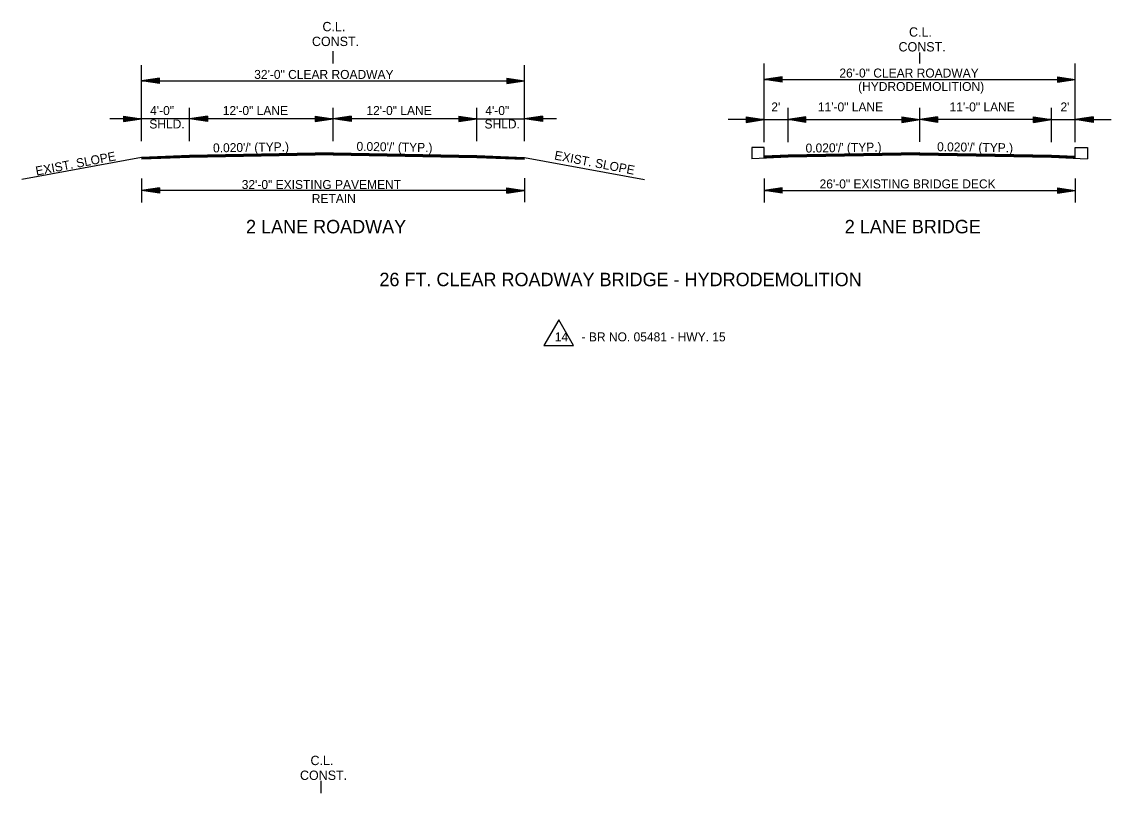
# Model space of a CAD drawing. Extents: x 549600 to 1930787, y -1955432 to 596640.
# Drawn here: x 551102 to 552012, y -1951981 to -1951337 of the extents above; entities that cross this region are included whole.
import ezdxf

# ---------------------------------------------------------------- set-up
doc = ezdxf.new("R2010")
doc.units = 0
doc.layers.add('R_Border', color=7, linetype='Continuous')
doc.layers.add('S_AREA_CALC', color=7, linetype='Continuous')

msp = doc.modelspace()

# ---------------------------------------------------------------- linework, layer by layer
at = {"layer": 'R_Border'}
for p, q in [((551982.02, -1951418.62), (552012.02, -1951418.62)), ((551711.85, -1951441.93), (551711.84, -1951451.31)), ((551722.02, -1951441.93), (551711.85, -1951441.93)), ((551722.02, -1951450.73), (551722.02, -1951441.93)), ((551982.02, -1951450.73), (551982.02, -1951441.93)), ((551982.02, -1951441.93), (551992.18, -1951441.93)), ((551992.18, -1951441.93), (551992.2, -1951451.31)), ((551538.16, -1951607.28), (551562.96, -1951607.28))]:
    msp.add_line(p, q, dxfattribs=at)
msp.add_lwpolyline([(551562.96, -1951607.28), (551550.56, -1951585.81), (551538.16, -1951607.28)], dxfattribs=at)
at = {"layer": 'S_AREA_CALC'}
for p, q in [((551362.02, -1951371.79), (551362.02, -1951361.42)), ((551852.02, -1951371.67), (551852.02, -1951362.37)), ((551202.02, -1951436.68), (551202.02, -1951373.17)), ((551522.02, -1951436.68), (551522.02, -1951373.17)), ((551722.02, -1951437.45), (551722.02, -1951371.72)), ((551982.02, -1951437.45), (551982.02, -1951371.72)), ((551217.02, -1951384.01), (551202.02, -1951386.26)), ((551202.02, -1951386.26), (551522.02, -1951386.26)), ((551217.02, -1951388.51), (551202.02, -1951386.26)), ((551217.02, -1951384.39), (551204.52, -1951386.26)), ((551217.02, -1951388.14), (551204.52, -1951386.26)), ((551217.02, -1951384.77), (551207.1, -1951386.26)), ((551217.02, -1951387.75), (551207.1, -1951386.26)), ((551217.02, -1951385.14), (551209.6, -1951386.26)), ((551217.02, -1951387.38), (551209.6, -1951386.26)), ((551217.02, -1951385.53), (551212.14, -1951386.26)), ((551217.02, -1951386.99), (551212.14, -1951386.26)), ((551217.02, -1951385.91), (551214.65, -1951386.26)), ((551217.02, -1951386.61), (551214.65, -1951386.26)), ((551217.02, -1951388.51), (551217.02, -1951384.01)), ((551507.02, -1951384.01), (551522.02, -1951386.26)), ((551507.02, -1951384.01), (551507.02, -1951388.51)), ((551507.02, -1951384.39), (551519.51, -1951386.26)), ((551507.02, -1951384.77), (551516.93, -1951386.26)), ((551507.02, -1951385.14), (551514.44, -1951386.26)), ((551507.02, -1951385.53), (551511.89, -1951386.26)), ((551507.02, -1951385.91), (551509.39, -1951386.26)), ((551507.02, -1951388.51), (551522.02, -1951386.26)), ((551507.02, -1951387), (551511.89, -1951386.26)), ((551507.02, -1951387.75), (551516.93, -1951386.26)), ((551507.02, -1951388.14), (551519.51, -1951386.26)), ((551507.02, -1951387.38), (551514.44, -1951386.26)), ((551507.02, -1951386.61), (551509.39, -1951386.26)), ((551737.02, -1951382.84), (551722.02, -1951385.09)), ((551722.02, -1951385.09), (551980.02, -1951385.09)), ((551737.02, -1951387.34), (551722.02, -1951385.09)), ((551737.02, -1951383.21), (551724.52, -1951385.09)), ((551737.02, -1951386.96), (551724.52, -1951385.09)), ((551737.02, -1951383.59), (551727.1, -1951385.09)), ((551737.02, -1951386.58), (551727.1, -1951385.09)), ((551737.02, -1951383.97), (551729.6, -1951385.09)), ((551737.02, -1951386.2), (551729.6, -1951385.09)), ((551737.02, -1951384.35), (551732.14, -1951385.09)), ((551737.02, -1951385.81), (551732.14, -1951385.09)), ((551737.02, -1951384.73), (551734.65, -1951385.09)), ((551737.02, -1951385.44), (551734.65, -1951385.09)), ((551737.02, -1951387.34), (551737.02, -1951382.84)), ((551967.02, -1951382.84), (551982.02, -1951385.09)), ((551967.02, -1951382.84), (551967.02, -1951387.34)), ((551967.02, -1951383.21), (551979.51, -1951385.09)), ((551967.02, -1951383.59), (551976.93, -1951385.09)), ((551967.02, -1951383.97), (551974.44, -1951385.09)), ((551967.02, -1951384.36), (551971.89, -1951385.09)), ((551967.02, -1951384.73), (551969.39, -1951385.09)), ((551967.02, -1951387.34), (551982.02, -1951385.09)), ((551967.02, -1951385.82), (551971.89, -1951385.09)), ((551967.02, -1951386.58), (551976.93, -1951385.09)), ((551967.02, -1951386.96), (551979.51, -1951385.09)), ((551967.02, -1951386.2), (551974.44, -1951385.09)), ((551967.02, -1951385.44), (551969.39, -1951385.09)), ((551242.02, -1951436.68), (551242.02, -1951408.73)), ((551362.02, -1951436.68), (551362.02, -1951408.73)), ((551482.02, -1951436.68), (551482.02, -1951408.73)), ((551742.02, -1951437.45), (551742.02, -1951408.73)), ((551852.02, -1951437.28), (551852.02, -1951408.73)), ((551962.02, -1951437.45), (551962.02, -1951408.73)), ((551202.02, -1951417.92), (551175.5, -1951417.92)), ((551187.02, -1951415.67), (551202.02, -1951417.92)), ((551187.02, -1951415.67), (551187.02, -1951420.17)), ((551187.02, -1951416.05), (551199.51, -1951417.92)), ((551187.02, -1951416.43), (551196.93, -1951417.92)), ((551187.02, -1951416.8), (551194.44, -1951417.92)), ((551187.02, -1951417.19), (551191.89, -1951417.92)), ((551187.02, -1951417.57), (551189.39, -1951417.92)), ((551187.02, -1951420.17), (551202.02, -1951417.92)), ((551187.02, -1951418.66), (551191.89, -1951417.92)), ((551187.02, -1951419.41), (551196.93, -1951417.92)), ((551187.02, -1951419.8), (551199.51, -1951417.92)), ((551187.02, -1951419.04), (551194.44, -1951417.92)), ((551187.02, -1951418.27), (551189.39, -1951417.92)), ((551242.02, -1951417.92), (551202.02, -1951417.92)), ((551257.02, -1951415.67), (551242.02, -1951417.92)), ((551362.02, -1951417.92), (551242.02, -1951417.92)), ((551257.02, -1951420.17), (551242.02, -1951417.92)), ((551257.02, -1951416.05), (551244.52, -1951417.92)), ((551257.02, -1951419.8), (551244.52, -1951417.92)), ((551257.02, -1951416.43), (551247.1, -1951417.92)), ((551257.02, -1951419.41), (551247.1, -1951417.92)), ((551257.02, -1951416.8), (551249.6, -1951417.92)), ((551257.02, -1951419.04), (551249.6, -1951417.92)), ((551257.02, -1951417.19), (551252.14, -1951417.92)), ((551257.02, -1951418.66), (551252.14, -1951417.92)), ((551257.02, -1951417.57), (551254.65, -1951417.92)), ((551257.02, -1951418.27), (551254.65, -1951417.92)), ((551257.02, -1951415.67), (551257.02, -1951420.17)), ((551347.02, -1951415.67), (551362.02, -1951417.92)), ((551347.02, -1951415.67), (551347.02, -1951420.17)), ((551347.02, -1951416.05), (551359.51, -1951417.92)), ((551347.02, -1951416.43), (551356.93, -1951417.92)), ((551347.02, -1951416.8), (551354.44, -1951417.92)), ((551347.02, -1951417.19), (551351.89, -1951417.92)), ((551347.02, -1951417.57), (551349.39, -1951417.92)), ((551347.02, -1951420.17), (551362.02, -1951417.92)), ((551347.02, -1951418.66), (551351.89, -1951417.92)), ((551347.02, -1951419.41), (551356.93, -1951417.92)), ((551347.02, -1951419.8), (551359.51, -1951417.92)), ((551347.02, -1951419.04), (551354.44, -1951417.92)), ((551347.02, -1951418.27), (551349.39, -1951417.92)), ((551377.02, -1951415.67), (551362.02, -1951417.92)), ((551482.02, -1951417.92), (551362.02, -1951417.92)), ((551377.02, -1951420.17), (551362.02, -1951417.92)), ((551377.02, -1951416.05), (551364.52, -1951417.92)), ((551377.02, -1951419.8), (551364.52, -1951417.92)), ((551377.02, -1951416.43), (551367.1, -1951417.92)), ((551377.02, -1951419.41), (551367.1, -1951417.92)), ((551377.02, -1951416.8), (551369.6, -1951417.92)), ((551377.02, -1951419.04), (551369.6, -1951417.92)), ((551377.02, -1951417.19), (551372.14, -1951417.92)), ((551377.02, -1951418.66), (551372.14, -1951417.92)), ((551377.02, -1951417.57), (551374.65, -1951417.92)), ((551377.02, -1951418.27), (551374.65, -1951417.92)), ((551377.02, -1951415.67), (551377.02, -1951420.17)), ((551467.02, -1951415.67), (551482.02, -1951417.92)), ((551467.02, -1951415.67), (551467.02, -1951420.17)), ((551467.02, -1951416.05), (551479.51, -1951417.92)), ((551467.02, -1951416.43), (551476.93, -1951417.92)), ((551467.02, -1951416.8), (551474.44, -1951417.92)), ((551467.02, -1951417.19), (551471.89, -1951417.92)), ((551467.02, -1951417.57), (551469.39, -1951417.92)), ((551467.02, -1951420.17), (551482.02, -1951417.92)), ((551467.02, -1951418.66), (551471.89, -1951417.92)), ((551467.02, -1951419.41), (551476.93, -1951417.92)), ((551467.02, -1951419.8), (551479.51, -1951417.92)), ((551467.02, -1951419.04), (551474.44, -1951417.92)), ((551467.02, -1951418.27), (551469.39, -1951417.92)), ((551482.02, -1951417.92), (551522.02, -1951417.92)), ((551537.02, -1951415.67), (551522.02, -1951417.92)), ((551537.02, -1951420.17), (551522.02, -1951417.92)), ((551548.54, -1951417.92), (551522.02, -1951417.92)), ((551537.02, -1951416.05), (551524.52, -1951417.92)), ((551537.02, -1951419.8), (551524.52, -1951417.92)), ((551537.02, -1951416.43), (551527.1, -1951417.92)), ((551537.02, -1951419.41), (551527.1, -1951417.92)), ((551537.02, -1951416.8), (551529.6, -1951417.92)), ((551537.02, -1951419.04), (551529.6, -1951417.92)), ((551537.02, -1951417.19), (551532.14, -1951417.92)), ((551537.02, -1951418.66), (551532.14, -1951417.92)), ((551537.02, -1951417.57), (551534.65, -1951417.92)), ((551537.02, -1951418.27), (551534.65, -1951417.92)), ((551537.02, -1951415.67), (551537.02, -1951420.17)), ((551722.02, -1951418.62), (551692.02, -1951418.62)), ((551707.02, -1951416.37), (551722.02, -1951418.62)), ((551707.02, -1951416.37), (551707.02, -1951420.87)), ((551707.02, -1951416.75), (551719.51, -1951418.62)), ((551707.02, -1951417.13), (551716.93, -1951418.62)), ((551707.02, -1951417.51), (551714.44, -1951418.62)), ((551707.02, -1951417.9), (551711.89, -1951418.62)), ((551707.02, -1951418.27), (551709.39, -1951418.62)), ((551707.02, -1951420.87), (551722.02, -1951418.62)), ((551707.02, -1951419.36), (551711.89, -1951418.62)), ((551707.02, -1951420.12), (551716.93, -1951418.62)), ((551707.02, -1951420.5), (551719.51, -1951418.62)), ((551707.02, -1951419.74), (551714.44, -1951418.62)), ((551707.02, -1951418.98), (551709.39, -1951418.62)), ((551722.02, -1951418.62), (551742.02, -1951418.62)), ((551757.02, -1951416.37), (551742.02, -1951418.62)), ((551757.02, -1951420.87), (551742.02, -1951418.62)), ((551742.02, -1951418.62), (551852.02, -1951418.62)), ((551757.02, -1951416.75), (551744.52, -1951418.62)), ((551757.02, -1951420.5), (551744.52, -1951418.62)), ((551757.02, -1951417.13), (551747.1, -1951418.62)), ((551757.02, -1951420.12), (551747.1, -1951418.62)), ((551757.02, -1951417.51), (551749.6, -1951418.62)), ((551757.02, -1951419.74), (551749.6, -1951418.62)), ((551757.02, -1951417.89), (551752.14, -1951418.62)), ((551757.02, -1951419.35), (551752.14, -1951418.62)), ((551757.02, -1951418.27), (551754.65, -1951418.62)), ((551757.02, -1951418.98), (551754.65, -1951418.62)), ((551757.02, -1951420.87), (551757.02, -1951416.37)), ((551837.02, -1951416.37), (551852.02, -1951418.62)), ((551837.02, -1951416.37), (551837.02, -1951420.87)), ((551837.02, -1951416.75), (551849.51, -1951418.62)), ((551837.02, -1951417.13), (551846.93, -1951418.62)), ((551837.02, -1951417.51), (551844.44, -1951418.62)), ((551837.02, -1951417.9), (551841.89, -1951418.62)), ((551837.02, -1951418.27), (551839.39, -1951418.62)), ((551837.02, -1951420.87), (551852.02, -1951418.62)), ((551837.02, -1951419.36), (551841.89, -1951418.62)), ((551837.02, -1951420.12), (551846.93, -1951418.62)), ((551837.02, -1951420.5), (551849.51, -1951418.62)), ((551837.02, -1951419.74), (551844.44, -1951418.62)), ((551837.02, -1951418.98), (551839.39, -1951418.62)), ((551867.02, -1951416.37), (551852.02, -1951418.62)), ((551962.02, -1951418.62), (551852.02, -1951418.62)), ((551867.02, -1951420.87), (551852.02, -1951418.62)), ((551867.02, -1951416.75), (551854.52, -1951418.62)), ((551867.02, -1951420.5), (551854.52, -1951418.62)), ((551867.02, -1951417.13), (551857.1, -1951418.62)), ((551867.02, -1951420.12), (551857.1, -1951418.62)), ((551867.02, -1951417.51), (551859.6, -1951418.62)), ((551867.02, -1951419.74), (551859.6, -1951418.62)), ((551867.02, -1951417.9), (551862.14, -1951418.62)), ((551867.02, -1951419.36), (551862.14, -1951418.62)), ((551867.02, -1951418.27), (551864.65, -1951418.62)), ((551867.02, -1951418.98), (551864.65, -1951418.62)), ((551867.02, -1951416.37), (551867.02, -1951420.87)), ((551947.02, -1951416.37), (551962.02, -1951418.62)), ((551947.02, -1951420.87), (551947.02, -1951416.37)), ((551947.02, -1951416.75), (551959.51, -1951418.62)), ((551947.02, -1951417.13), (551956.93, -1951418.62)), ((551947.02, -1951417.51), (551954.44, -1951418.62)), ((551947.02, -1951417.89), (551951.89, -1951418.62)), ((551947.02, -1951418.27), (551949.39, -1951418.62)), ((551947.02, -1951420.87), (551962.02, -1951418.62)), ((551947.02, -1951419.35), (551951.89, -1951418.62)), ((551947.02, -1951420.12), (551956.93, -1951418.62)), ((551947.02, -1951420.5), (551959.51, -1951418.62)), ((551947.02, -1951419.74), (551954.44, -1951418.62)), ((551947.02, -1951418.98), (551949.39, -1951418.62)), ((551962.02, -1951418.62), (551982.02, -1951418.62)), ((551997.02, -1951416.37), (551982.02, -1951418.62)), ((551997.02, -1951420.87), (551982.02, -1951418.62)), ((551997.02, -1951416.75), (551984.52, -1951418.62)), ((551997.02, -1951420.5), (551984.52, -1951418.62)), ((551997.02, -1951417.13), (551987.1, -1951418.62)), ((551997.02, -1951420.12), (551987.1, -1951418.62)), ((551997.02, -1951417.51), (551989.6, -1951418.62)), ((551997.02, -1951419.74), (551989.6, -1951418.62)), ((551997.02, -1951417.9), (551992.14, -1951418.62)), ((551997.02, -1951419.36), (551992.14, -1951418.62)), ((551997.02, -1951418.27), (551994.65, -1951418.62)), ((551997.02, -1951418.98), (551994.65, -1951418.62)), ((551997.02, -1951416.37), (551997.02, -1951420.87)), ((551202.02, -1951450.23), (551101.95, -1951468.61)), ((551242.02, -1951448.63), (551202.02, -1951450.23)), ((551242.02, -1951448.93), (551202.02, -1951450.53)), ((551242.02, -1951449.23), (551202.02, -1951450.83)), ((551242.02, -1951449.53), (551202.02, -1951451.13)), ((551242.02, -1951449.83), (551202.02, -1951451.43)), ((551242.02, -1951450.13), (551202.02, -1951451.73)), ((551362.02, -1951446.23), (551242.02, -1951448.63)), ((551362.02, -1951446.53), (551242.02, -1951448.93)), ((551362.02, -1951446.83), (551242.02, -1951449.23)), ((551362.02, -1951447.13), (551242.02, -1951449.53)), ((551362.02, -1951447.43), (551242.02, -1951449.83)), ((551362.02, -1951447.73), (551242.02, -1951450.13)), ((551362.02, -1951447.9), (551242.02, -1951450.3)), ((551362.02, -1951446.23), (551482.02, -1951448.63)), ((551362.02, -1951446.53), (551482.02, -1951448.93)), ((551362.02, -1951446.83), (551482.02, -1951449.23)), ((551362.02, -1951447.13), (551482.02, -1951449.53)), ((551362.02, -1951447.43), (551482.02, -1951449.83)), ((551362.02, -1951447.73), (551482.02, -1951450.13)), ((551362.02, -1951447.9), (551482.02, -1951450.3)), ((551482.02, -1951448.63), (551522.02, -1951450.23)), ((551482.02, -1951448.93), (551522.02, -1951450.53)), ((551482.02, -1951449.23), (551522.02, -1951450.83)), ((551482.02, -1951449.53), (551522.02, -1951451.13)), ((551482.02, -1951449.83), (551522.02, -1951451.43)), ((551482.02, -1951450.13), (551522.02, -1951451.73)), ((551522.02, -1951450.23), (551622.09, -1951468.61)), ((551742.02, -1951450.1), (551711.84, -1951451.31)), ((551742.02, -1951448.43), (551722.02, -1951449.23)), ((551742.02, -1951448.73), (551722.02, -1951449.53)), ((551742.02, -1951449.03), (551722.02, -1951449.83)), ((551742.02, -1951449.33), (551722.02, -1951450.13)), ((551742.02, -1951449.63), (551722.02, -1951450.43)), ((551742.02, -1951449.93), (551722.02, -1951450.73)), ((551852.02, -1951446.23), (551742.02, -1951448.43)), ((551852.02, -1951446.53), (551742.02, -1951448.73)), ((551852.03, -1951446.83), (551742.02, -1951449.03)), ((551852.04, -1951447.13), (551742.02, -1951449.33)), ((551852.04, -1951447.43), (551742.02, -1951449.63)), ((551852.05, -1951447.73), (551742.02, -1951449.93)), ((551852.05, -1951447.9), (551742.02, -1951450.1)), ((551851.98, -1951447.9), (551962.02, -1951450.1)), ((551851.99, -1951447.43), (551962.02, -1951449.63)), ((551851.99, -1951447.73), (551962.02, -1951449.93)), ((551852, -1951447.13), (551962.02, -1951449.33)), ((551852.01, -1951446.53), (551962.02, -1951448.73)), ((551852.01, -1951446.83), (551962.02, -1951449.03)), ((551852.02, -1951446.23), (551962.02, -1951448.43)), ((551962.02, -1951448.43), (551982.02, -1951449.23)), ((551962.02, -1951448.73), (551982.02, -1951449.53)), ((551962.02, -1951449.03), (551982.02, -1951449.83)), ((551962.02, -1951449.33), (551982.02, -1951450.13)), ((551962.02, -1951449.63), (551982.02, -1951450.43)), ((551962.02, -1951449.93), (551982.02, -1951450.73)), ((551962.02, -1951450.1), (551992.2, -1951451.31)), ((551202.02, -1951467.89), (551202.02, -1951487.89)), ((551522.02, -1951467.64), (551522.02, -1951487.64)), ((551722.02, -1951467.89), (551722.02, -1951487.89)), ((551982.02, -1951467.89), (551982.02, -1951487.89)), ((551217.02, -1951475.64), (551202.02, -1951477.89)), ((551217.02, -1951476.01), (551204.52, -1951477.89)), ((551217.02, -1951476.4), (551207.1, -1951477.89)), ((551217.02, -1951476.77), (551209.6, -1951477.89)), ((551217.02, -1951477.16), (551212.14, -1951477.89)), ((551217.02, -1951477.54), (551214.65, -1951477.89)), ((551217.02, -1951475.64), (551217.02, -1951480.14)), ((551507.02, -1951475.64), (551522.02, -1951477.89)), ((551507.02, -1951480.14), (551507.02, -1951475.64)), ((551507.02, -1951476.01), (551519.51, -1951477.89)), ((551507.02, -1951476.4), (551516.93, -1951477.89)), ((551507.02, -1951476.77), (551514.44, -1951477.89)), ((551507.02, -1951477.15), (551511.89, -1951477.89)), ((551507.02, -1951477.54), (551509.39, -1951477.89)), ((551737.02, -1951475.64), (551722.02, -1951477.89)), ((551737.02, -1951476.01), (551724.52, -1951477.89)), ((551737.02, -1951476.4), (551727.1, -1951477.89)), ((551737.02, -1951476.77), (551729.6, -1951477.89)), ((551737.02, -1951477.15), (551732.14, -1951477.89)), ((551737.02, -1951477.54), (551734.65, -1951477.89)), ((551737.02, -1951480.14), (551737.02, -1951475.64)), ((551967.02, -1951475.64), (551982.02, -1951477.89)), ((551967.02, -1951475.64), (551967.02, -1951480.14)), ((551967.02, -1951476.01), (551979.51, -1951477.89)), ((551967.02, -1951476.4), (551976.93, -1951477.89)), ((551967.02, -1951476.77), (551974.44, -1951477.89)), ((551967.02, -1951477.16), (551971.89, -1951477.89)), ((551967.02, -1951477.54), (551969.39, -1951477.89)), ((551217.02, -1951480.14), (551202.02, -1951477.89)), ((551522.02, -1951477.89), (551202.02, -1951477.89)), ((551217.02, -1951479.76), (551204.52, -1951477.89)), ((551217.02, -1951479.38), (551207.1, -1951477.89)), ((551217.02, -1951479.01), (551209.6, -1951477.89)), ((551217.02, -1951478.62), (551212.14, -1951477.89)), ((551217.02, -1951478.24), (551214.65, -1951477.89)), ((551507.02, -1951480.14), (551522.02, -1951477.89)), ((551507.02, -1951478.62), (551511.89, -1951477.89)), ((551507.02, -1951479.38), (551516.93, -1951477.89)), ((551507.02, -1951479.76), (551519.51, -1951477.89)), ((551507.02, -1951479.01), (551514.44, -1951477.89)), ((551507.02, -1951478.24), (551509.39, -1951477.89)), ((551722.02, -1951477.89), (551982.02, -1951477.89)), ((551737.02, -1951480.14), (551722.02, -1951477.89)), ((551737.02, -1951479.76), (551724.52, -1951477.89)), ((551737.02, -1951479.38), (551727.1, -1951477.89)), ((551737.02, -1951479.01), (551729.6, -1951477.89)), ((551737.02, -1951478.62), (551732.14, -1951477.89)), ((551737.02, -1951478.24), (551734.65, -1951477.89)), ((551967.02, -1951480.14), (551982.02, -1951477.89)), ((551967.02, -1951478.62), (551971.89, -1951477.89)), ((551967.02, -1951479.38), (551976.93, -1951477.89)), ((551967.02, -1951479.76), (551979.51, -1951477.89)), ((551967.02, -1951479.01), (551974.44, -1951477.89)), ((551967.02, -1951478.24), (551969.39, -1951477.89)), ((551352.02, -1951981.45), (551352.02, -1951971.08))]:
    msp.add_line(p, q, dxfattribs=at)

# ---------------------------------------------------------------- texts
at = {"layer": 'R_Border'}
for s, p in [('14', (551547.19, -1951603.88)), ('- BR NO. 05481 - HWY. 15', (551569.56, -1951603.88))]:
    msp.add_text(s, height=7.5, dxfattribs=at).set_placement(p)
at = {"layer": 'S_AREA_CALC'}
for s, height, p in [('C.L.', 7.8, (551353.12, -1951344.75)), ('CONST.', 7.8, (551344.34, -1951357.12)), ('C.L.', 7.8, (551843.12, -1951349.27)), ('CONST.', 7.8, (551834.34, -1951361.64)), ('32\'-0" CLEAR ROADWAY', 7.5, (551296.11, -1951384.59)), ('26\'-0" CLEAR ROADWAY ', 7.5, (551784.93, -1951383.42)), ('(HYDRODEMOLITION)', 7.5, (551800.58, -1951394.67)), ("2'", 7.5, (551728.06, -1951411.76)), ('11\'-0" LANE', 7.5, (551766.96, -1951411.76)), ('11\'-0" LANE', 7.5, (551876.96, -1951411.76)), ("2'", 7.5, (551969.62, -1951411.76)), ('4\'-0"', 7.5, (551209.17, -1951414.75)), ('12\'-0" LANE', 7.5, (551269.84, -1951414.75)), ('12\'-0" LANE', 7.5, (551389.84, -1951414.75)), ('4\'-0"', 7.5, (551489.17, -1951414.75)), ('SHLD.', 7.5, (551208.49, -1951426)), ('SHLD.', 7.5, (551488.49, -1951426)), ('26\'-0" EXISTING BRIDGE DECK', 7.5, (551768.4, -1951476.06)), ('32\'-0" EXISTING PAVEMENT', 7.5, (551285.69, -1951476.57)), ('RETAIN', 7.5, (551344.21, -1951488.31)), ('2 LANE ROADWAY', 11.25, (551289.29, -1951513.61)), ('2 LANE BRIDGE', 11.25, (551789.42, -1951513.61)), ('26 FT. CLEAR ROADWAY BRIDGE - HYDRODEMOLITION', 11.25, (551400.69, -1951557.79)), ('C.L.', 7.8, (551343.12, -1951957.98)), ('CONST.', 7.8, (551334.34, -1951970.35))]:
    msp.add_text(s, height=height, dxfattribs=at).set_placement(p)
for s, rotation, p in [("0.020'/' (TYP.)", 0.97192, (551261.76, -1951446.02)), ("0.020'/' (TYP.)", 359.02808, (551381.5, -1951444.65)), ("0.020'/' (TYP.)", 0.87191, (551756.76, -1951446.18)), ("0.020'/' (TYP.)", 359.12809, (551866.51, -1951444.96)), ('EXIST. SLOPE', 10.88286, (551114.23, -1951465.39)), ('EXIST. SLOPE', 349.11714, (551546.4, -1951451.83))]:
    msp.add_text(s, height=7.5, rotation=rotation, dxfattribs=at).set_placement(p)

doc.saveas('drawing.dxf')
